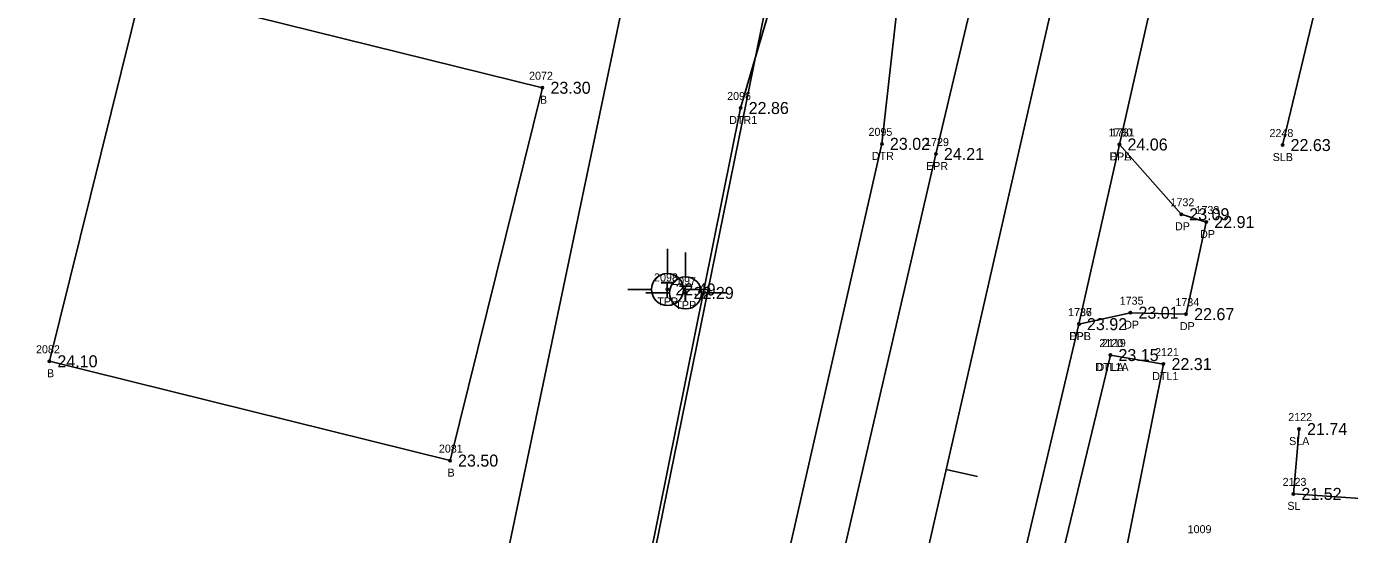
# Model space of a CAD drawing. Extents: x 2654414 to 2656963, y 761776 to 764965.
# Drawn here: x 2655340.6 to 2655506, y 762096.2 to 762159.7 of the extents above; entities that cross this region are included whole.
import ezdxf

# ---------------------------------------------------------------- set-up
doc = ezdxf.new("R2010")
doc.units = 0
for name, color, linetype in [('Default', 7, 'Continuous'), ('RD_EX_Bldg', 7, 'Continuous'), ('RD_EX_Bldg_txCode', 7, 'Continuous'), ('RD_EX_Driveway', 7, 'Continuous'), ('RD_EX_Driveway_txCode', 7, 'Continuous'), ('RD_EX_DV_Prop_txCode', 7, 'Continuous'), ('RD_EX_Fence_Other', 7, 'Continuous'), ('RD_EX_H2O', 7, 'Continuous'), ('RD_EX_H2O_txCode', 7, 'Continuous'), ('RD_EX_Road', 7, 'Continuous'), ('RD_EX_Road_txCode', 7, 'Continuous'), ('RD_EX_TX_Bldg_ELEV', 7, 'Continuous'), ('RD_EX_TX_Driveway_ELEV', 7, 'Continuous'), ('RD_EX_TX_H2O_ELEV', 7, 'Continuous'), ('RD_EX_TX_Road_ELEV', 7, 'Continuous'), ('RD_EX_TX_UT_ELEV', 7, 'Continuous'), ('RD_EX_TX_VEG_ELEV', 7, 'Continuous'), ('RD_EX_UT', 7, 'Continuous'), ('RD_EX_UT_txCode', 7, 'Continuous'), ('RD_EX_VEG', 7, 'Continuous'), ('RD_EX_VEG_txCode', 7, 'Continuous'), ('RD_HC_Cl', 7, 'Continuous'), ('RD_HC_Data_Tic', 7, 'Continuous'), ('RD_SMD_Locator', 7, 'Continuous')]:
    doc.layers.add(name, color=color, linetype=linetype)

msp = doc.modelspace()

# ---------------------------------------------------------------- linework, layer by layer
at = {"layer": 'Default'}
msp.add_line((2656050.51, 764712.37), (2655383.26, 761787.51), dxfattribs=at)
at = {"layer": 'RD_EX_Bldg'}
msp.add_lwpolyline([(2655355.02, 762164.47), (2655405.09, 762152.06), (2655393.54, 762105.47), (2655343.47, 762117.88), (2655355.02, 762164.47)], dxfattribs=at)
at = {"layer": 'RD_EX_Driveway'}
msp.add_lwpolyline([(2655477.2, 762144.97), (2655484.92, 762136.25), (2655488.05, 762135.28), (2655485.53, 762123.77), (2655478.57, 762123.95), (2655472.14, 762122.52)], dxfattribs=at)
at = {"layer": 'RD_EX_Fence_Other'}
msp.add_lwpolyline([(2655431.78, 762175.86), (2655417.3, 762172.91), (2655393.28, 762058.24), (2655393.28, 762058.24), (2655337.57, 762053.75), (2655251.71, 762069.62), (2655221.44, 762090.34)], dxfattribs=at)
at = {"layer": 'RD_EX_H2O'}
for points in [[(2655450.32, 762170.31), (2655445.39, 762174.97), (2655437.79, 762176.61), (2655429.86, 762149.53), (2655410.49, 762053.38), (2655410.35, 762043.63), (2655388.95, 762049.63)], [(2655450.32, 762170.31), (2655447.51, 762145.05), (2655428.44, 762061.32), (2655427.05, 762050.54), (2655425.43, 762042.76), (2655423.63, 762041.01), (2655404.09, 761950.81), (2655382.1, 761859.05), (2655367.49, 761795.82)], [(2655476.07, 762118.66), (2655457.95, 762043.6), (2655455.32, 762034.02), (2655437.36, 761949.13), (2655416.41, 761851.26), (2655413.59, 761836.57), (2655406.69, 761818.38), (2655416.71, 761813.93)], [(2655476.07, 762118.66), (2655482.7, 762117.53), (2655467.21, 762040.56), (2655459.71, 762010.57)]]:
    msp.add_lwpolyline(points, dxfattribs=at)
at = {"layer": 'RD_EX_Road'}
for points in [[(2655700.99, 763232.28), (2655693.55, 763198.57), (2655671.65, 763102.04), (2655649.04, 763001.06), (2655627.27, 762906.23), (2655605, 762809.37), (2655598.99, 762783.09), (2655583.65, 762714.14), (2655561.97, 762618.32), (2655556.36, 762593.84), (2655548.11, 762557.14), (2655540.1, 762522.48), (2655518.03, 762425.04), (2655496.48, 762329.56), (2655475.55, 762236.62), (2655473.2, 762226.14), (2655466.57, 762197.5), (2655460.06, 762168.16), (2655454.26, 762143.78), (2655432.5, 762049.88), (2655410.7, 761955.51), (2655388.17, 761858.43), (2655373.5, 761793.95)], [(2655670.04, 762995.18), (2655648.57, 762900.67), (2655631.27, 762824.03), (2655626.67, 762802.87), (2655621.78, 762781.91), (2655611.71, 762738.43), (2655604.93, 762708.62), (2655582.64, 762610.54), (2655576.46, 762583.32), (2655561.41, 762517.24), (2655539.15, 762414.81), (2655531.98, 762386.15), (2655517.98, 762324.29), (2655508.17, 762280.15), (2655501.46, 762251.6), (2655496.92, 762232.09), (2655477.2, 762144.97), (2655472.14, 762122.52), (2655453.74, 762045.1), (2655431.79, 761949.92), (2655409.76, 761853.25), (2655401.25, 761816.42), (2655394.61, 761787.37)]]:
    msp.add_lwpolyline(points, dxfattribs=at)
at = {"layer": 'RD_EX_UT'}
for p, q in [((2655420.71, 762131.93), (2655420.71, 762128.86)), ((2655422.97, 762131.49), (2655422.97, 762128.42)), ((2655415.78, 762126.87), (2655418.71, 762126.87)), ((2655418.03, 762126.43), (2655420.97, 762126.43)), ((2655422.71, 762126.87), (2655425.78, 762126.87)), ((2655424.97, 762126.43), (2655428.03, 762126.43))]:
    msp.add_line(p, q, dxfattribs=at)
for centre in [(2655420.71, 762126.86), (2655422.97, 762126.42)]:
    msp.add_circle(centre, 2, dxfattribs=at)
at = {"layer": 'RD_EX_VEG'}
msp.add_line((2655518.28, 762230.88), (2655497.58, 762144.9), dxfattribs=at)
for points in [[(2655435.66, 762175.38), (2655407.48, 762036.84), (2655372.67, 761884.87)], [(2655499.64, 762109.41), (2655498.94, 762101.31), (2655513.25, 762100.32)]]:
    msp.add_lwpolyline(points, dxfattribs=at)
at = {"layer": 'RD_HC_Cl'}
msp.add_line((2656050.51, 764712.37), (2655383.26, 761787.51), dxfattribs=at)
at = {"layer": 'RD_HC_Data_Tic'}
msp.add_line((2655455.55, 762104.37), (2655459.45, 762103.48), dxfattribs=at)
at = {"layer": 'RD_SMD_Locator'}
for centre in [(2655405.09, 762152.06), (2655429.86, 762149.53), (2655447.51, 762145.05), (2655477.2, 762144.97), (2655477.2, 762144.97), (2655497.58, 762144.9), (2655454.26, 762143.78), (2655484.92, 762136.25), (2655488.05, 762135.28), (2655420.71, 762126.86), (2655422.97, 762126.42), (2655478.57, 762123.95), (2655485.53, 762123.77), (2655472.14, 762122.52), (2655472.14, 762122.52), (2655343.47, 762117.88), (2655476.07, 762118.66), (2655476.07, 762118.66), (2655482.7, 762117.53), (2655499.64, 762109.41), (2655393.54, 762105.47), (2655498.94, 762101.31)]:
    msp.add_circle(centre, 0.15, dxfattribs=at)

# ---------------------------------------------------------------- texts
at = {"layer": 'RD_EX_Bldg_txCode'}
for s, p in [('2072', (2655403.42, 762153.06)), ('B', (2655404.78, 762150.06)), ('2082', (2655341.8, 762118.88)), ('B', (2655343.17, 762115.88)), ('2081', (2655392.15, 762106.47)), ('B', (2655393.23, 762103.47))]:
    msp.add_text(s, height=1, dxfattribs=at).set_placement(p)
at = {"layer": 'RD_EX_Driveway_txCode'}
for s, p in [('1731', (2655476.14, 762145.97)), ('DPA', (2655475.94, 762142.97)), ('1732', (2655483.58, 762137.25)), ('1733', (2655486.7, 762136.28)), ('DP', (2655484.14, 762134.25)), ('DP', (2655487.27, 762133.28)), ('1736', (2655470.77, 762123.52)), ('1735', (2655477.23, 762124.95)), ('1734', (2655484.19, 762124.77)), ('DP', (2655477.79, 762121.95)), ('DPB', (2655470.89, 762120.52)), ('DP', (2655484.75, 762121.77))]:
    msp.add_text(s, height=1, dxfattribs=at).set_placement(p)
at = {"layer": 'RD_EX_DV_Prop_txCode'}
msp.add_text('1009', height=1, dxfattribs=at).set_placement((2655485.72, 762096.4))
at = {"layer": 'RD_EX_H2O_txCode'}
for s, p in [('2096', (2655428.17, 762150.53)), ('DTR1', (2655428.43, 762147.53)), ('2095', (2655445.84, 762146.05)), ('DTR', (2655446.25, 762143.05)), ('2120', (2655474.68, 762119.66)), ('2119', (2655475.01, 762119.66)), ('2121', (2655481.64, 762118.53)), ('DTL1A', (2655474.17, 762116.66)), ('DTLA', (2655474.34, 762116.66)), ('DTL1', (2655481.3, 762115.53))]:
    msp.add_text(s, height=1, dxfattribs=at).set_placement(p)
at = {"layer": 'RD_EX_Road_txCode'}
for s, p in [('1730', (2655475.82, 762145.97)), ('1729', (2655452.91, 762144.78)), ('EPR', (2655453.03, 762141.78)), ('EPL', (2655476, 762142.97)), ('1737', (2655470.79, 762123.52)), ('EPL', (2655470.93, 762120.52))]:
    msp.add_text(s, height=1, dxfattribs=at).set_placement(p)
at = {"layer": 'RD_EX_TX_Bldg_ELEV'}
for s, p in [('23.30', (2655406.09, 762151.31)), ('24.10', (2655344.47, 762117.13)), ('23.50', (2655394.54, 762104.72))]:
    msp.add_text(s, height=1.5, dxfattribs=at).set_placement(p)
at = {"layer": 'RD_EX_TX_Driveway_ELEV'}
for s, p in [('24.06', (2655478.2, 762144.22)), ('23.09', (2655485.92, 762135.5)), ('22.91', (2655489.05, 762134.53)), ('23.01', (2655479.57, 762123.2)), ('22.67', (2655486.53, 762123.02)), ('23.92', (2655473.14, 762121.77))]:
    msp.add_text(s, height=1.5, dxfattribs=at).set_placement(p)
at = {"layer": 'RD_EX_TX_H2O_ELEV'}
for s, p in [('22.86', (2655430.86, 762148.78)), ('23.02', (2655448.51, 762144.3)), ('23.15', (2655477.07, 762117.91)), ('23.15', (2655477.07, 762117.91)), ('22.31', (2655483.7, 762116.78))]:
    msp.add_text(s, height=1.5, dxfattribs=at).set_placement(p)
at = {"layer": 'RD_EX_TX_Road_ELEV'}
for s, p in [('24.21', (2655455.26, 762143.03)), ('24.06', (2655478.2, 762144.22)), ('23.92', (2655473.14, 762121.77))]:
    msp.add_text(s, height=1.5, dxfattribs=at).set_placement(p)
at = {"layer": 'RD_EX_TX_UT_ELEV'}
for s, p in [('22.49', (2655421.71, 762126.11)), ('22.29', (2655423.97, 762125.67))]:
    msp.add_text(s, height=1.5, dxfattribs=at).set_placement(p)
at = {"layer": 'RD_EX_TX_VEG_ELEV'}
for s, p in [('22.63', (2655498.58, 762144.15)), ('21.74', (2655500.64, 762108.66)), ('21.52', (2655499.94, 762100.56))]:
    msp.add_text(s, height=1.5, dxfattribs=at).set_placement(p)
at = {"layer": 'RD_EX_UT'}
for p in [(2655419.86, 762125.81), (2655422.12, 762125.37)]:
    msp.add_text('T', height=2, dxfattribs=at).set_placement(p)
at = {"layer": 'RD_EX_UT_txCode'}
for s, p in [('2098', (2655419.04, 762127.86)), ('2097', (2655421.3, 762127.42)), ('TPP', (2655419.44, 762124.86)), ('TPP', (2655421.7, 762124.42))]:
    msp.add_text(s, height=1, dxfattribs=at).set_placement(p)
at = {"layer": 'RD_EX_VEG_txCode'}
for s, p in [('2248', (2655495.95, 762145.9)), ('SLB', (2655496.35, 762142.9)), ('2122', (2655498.29, 762110.41)), ('SLA', (2655498.4, 762107.41)), ('2123', (2655497.59, 762102.31)), ('SL', (2655498.18, 762099.31))]:
    msp.add_text(s, height=1, dxfattribs=at).set_placement(p)

doc.saveas('drawing.dxf')
